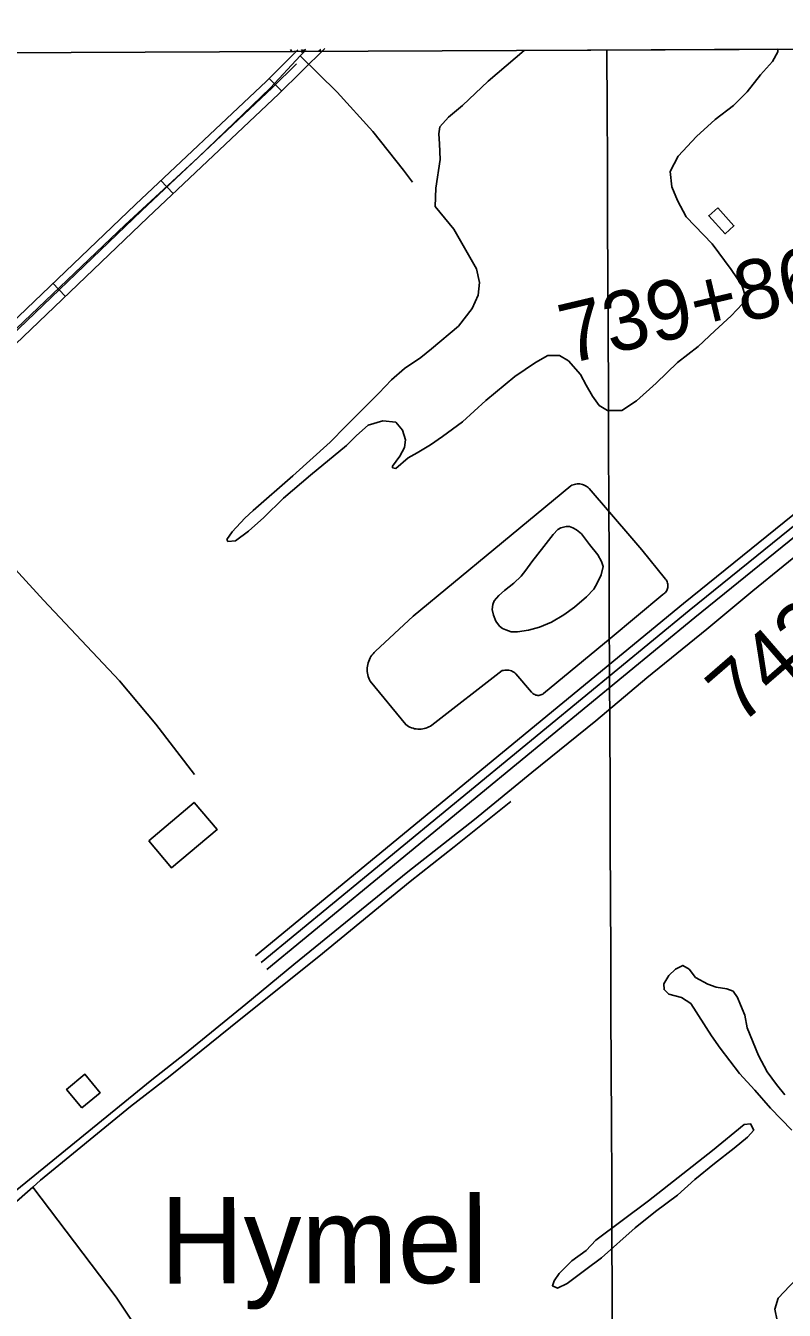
# Model space of a CAD drawing. Extents: x 3419139 to 3457078, y 540382 to 565875.
# Drawn here: x 3432771 to 3434044, y 561886 to 564042 of the extents above; entities that cross this region are included whole.
import ezdxf

# ---------------------------------------------------------------- set-up
doc = ezdxf.new("R2010")
doc.units = 0
for name, color, linetype in [('V-BLDG-OTLN', 7, 'Continuous'), ('V-DTCH-CNTR', 7, 'Continuous'), ('V-GRID-FRAM', 7, 'Continuous'), ('V-GRID-MAJR', 7, 'Continuous'), ('V-ROAD-CNTR', 7, 'Continuous'), ('V-SITE-VEGE', 7, 'Continuous'), ('V-SURV-IDEN', 7, 'Continuous'), ('V-TOPO-GNAM-IDEN', 7, 'Continuous'), ('V-TOPO-SHOR', 7, 'Continuous')]:
    doc.layers.add(name, color=color, linetype=linetype)

msp = doc.modelspace()

# ---------------------------------------------------------------- linework, layer by layer
at = {"layer": 'V-BLDG-OTLN'}
for points in [[(3433932.486, 563736.559), (3433959.841, 563706.183), (3433944.9420000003, 563692.764), (3433917.5870000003, 563723.142)], [(3432977.8000000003, 562674.241), (3433054.029, 562738.556), (3433092.343, 562693.1460000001), (3433016.112, 562628.828)], [(3432865.305231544, 562226.1325213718), (3432896.141169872, 562251.6104704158), (3432870.663220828, 562282.4464087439), (3432839.8272825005, 562256.969459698)]]:
    msp.add_lwpolyline(points, close=True, dxfattribs=at)
at = {"layer": 'V-DTCH-CNTR'}
msp.add_line((3432783.183, 562093.137), (3432923.051, 561908.684), dxfattribs=at)
for points in [[(3432938.477, 563707.723), (3433060.9590000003, 563820.824), (3433182.025, 563937.865), (3433231.957, 563991.1680000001), (3433236.307, 563995.813), (3433239.1768471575, 563998.8765962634)], [(3433236.307, 563995.813), (3433233.7615943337, 563998.8529670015)], [(3433231.957, 563991.1680000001), (3433293.8310000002, 563930.336), (3433353.68, 563864.311), (3433405.0640000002, 563799.696), (3433420.234, 563779.46)], [(3431177.463, 562042.332), (3431253.497, 562110.666), (3431343.14, 562191.228), (3431633.028, 562465.306), (3431891.076, 562710.152), (3431910.889, 562728.951), (3432168.3200000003, 562976.001), (3432453.037, 563247.807), (3432556.0330000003, 563344.78), (3432658.194, 563440.965), (3432938.477, 563707.723)], [(3432556.0330000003, 563344.78), (3432587.38, 563311.062), (3432801.3340000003, 563077.907), (3432928.685, 562942.61)], [(3432928.685, 562942.61), (3432989.757, 562870.042), (3433054.592, 562785.678)], [(3432946.943, 562228.147), (3433013.737, 562279.712), (3433132.537, 562375.681), (3433263.197, 562479.828), (3433416.6720000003, 562605.727), (3433490.411, 562664.06), (3433585.444, 562740.248)], [(3429853.677, 559689.77), (3430082.397, 559876.9720000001), (3430320.146, 560068.611), (3430369.134, 560108.099), (3430639.949, 560331.625), (3430956.687, 560585.09), (3431147.6240000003, 560740.107), (3431172.966, 560760.681), (3431507.447, 561035.132), (3431758.2800000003, 561244.818), (3432070.7600000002, 561502.703), (3432217.62, 561622.799), (3432367.171, 561745.096), (3432625.315, 561955.827), (3432637.14, 561965.481), (3432783.183, 562093.137), (3432796.327, 562104.628), (3432946.943, 562228.147)], [(3433171.662, 561519.687), (3433172.997, 561521.706), (3433174.142, 561523.84), (3433175.09, 561526.066), (3433175.832, 561528.372), (3433176.358, 561530.736), (3433176.669, 561533.136), (3433176.762, 561535.557), (3433176.632, 561537.973), (3433176.284, 561540.3690000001), (3433175.719, 561542.723), (3433174.943, 561545.0160000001), (3433173.96, 561547.228), (3433172.7800000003, 561549.344), (3433171.412, 561551.343), (3433128.203, 561617.155), (3433062.2090000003, 561712.954), (3432984.8910000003, 561816.403), (3432923.051, 561908.684)]]:
    msp.add_lwpolyline(points, dxfattribs=at)
at = {"layer": 'V-GRID-FRAM'}
msp.add_lwpolyline([(3423200.915, 563955.0750000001), (3454837.934, 564093.122), (3454925.2090000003, 545910.191), (3423272.322, 545772.075), (3423200.915, 563955.0750000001)], dxfattribs=at)
at = {"layer": 'V-GRID-MAJR'}
msp.add_spline([(3433823.284, 545818.1140000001), (3433797.732, 551876.0210000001), (3433772.166, 557937.014), (3433746.6010000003, 563998.023), (3433746.588, 564001.091)], degree=3, dxfattribs=at)
at = {"layer": 'V-ROAD-CNTR'}
for p, q in [((3433200.8595604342, 563932.014109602), (3433179.745602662, 563953.326066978)), ((3433018.59192497, 563760.34045295), (3432998.0379660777, 563782.1934092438)), ((3432837.681286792, 563587.9807976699), (3432816.9453282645, 563609.6607543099))]:
    msp.add_line(p, q, dxfattribs=at)
for points in [[(3433228.052506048, 564001.186971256), (3433175.329611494, 563948.9510757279), (3432955.3770514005, 563742.067489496), (3432693.621574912, 563491.7039902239), (3432347.7142667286, 563163.0626475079), (3431998.0889659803, 562828.740316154), (3431714.7705326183, 562560.7748520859), (3431334.6992927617, 562202.1065694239), (3431188.052586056, 562067.0418395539), (3431184.557593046, 562063.880845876), (3431137.0796880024, 562106.8997598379)], [(3433273.38141539, 564003.8669658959), (3433196.167569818, 563927.3651188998), (3432976.023010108, 563720.3015330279), (3432714.3215335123, 563469.9900336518), (3432368.412225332, 563141.34669094), (3432018.762924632, 562807.0003596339), (3431735.372491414, 562538.966895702), (3431355.1572518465, 562180.162613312), (3431208.276545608, 562044.881883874), (3431184.5375930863, 562023.4149268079), (3431183.118595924, 562024.7009242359)], [(3433218.0225261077, 563998.5889764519), (3433215.5525310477, 564001.9519697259)], [(3433241.205479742, 564002.063969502), (3433235.8784903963, 563999.6179743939), (3433234.1044939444, 564002.032969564)], [(3433266.3884293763, 564002.173969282), (3433263.084435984, 563999.266975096)], [(3433225.82151051, 563977.8610179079), (3433185.7485906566, 563938.158097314), (3432965.7000307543, 563731.184511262), (3432703.9715542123, 563480.8470119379), (3432358.06324603, 563152.204669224), (3432008.4259453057, 562817.870337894), (3431725.0715120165, 562549.870873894), (3431344.928272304, 562191.134591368), (3431198.1645658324, 562055.9618617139), (3431184.5475930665, 562043.6478863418), (3431127.0077081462, 562095.7837820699)], [(3434397.952166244, 563492.6499883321), (3434253.7054547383, 563378.1662173), (3433874.924212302, 563072.2048292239), (3433156.9806481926, 562481.481010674)], [(3434407.277147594, 563480.9010118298), (3434263.0804359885, 563366.457240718), (3433884.402193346, 563060.5788524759), (3433166.51162913, 562469.89803384)], [(3434416.6021289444, 563469.152035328), (3434272.455417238, 563354.7482641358), (3433893.88017439, 563048.9528757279), (3433176.0426100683, 562458.3150570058)], [(3433788.683, 563182.198), (3433716.782, 563265.385), (3433715.173, 563266.9400000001), (3433713.43, 563268.341), (3433711.566, 563269.582), (3433709.602, 563270.649), (3433707.548, 563271.5380000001), (3433705.4220000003, 563272.238), (3433703.245, 563272.746), (3433701.0270000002, 563273.055), (3433698.793, 563273.166), (3433696.558, 563273.076), (3433694.338, 563272.787), (3433692.1550000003, 563272.297), (3433690.025, 563271.618), (3433687.963, 563270.747), (3433685.989, 563269.697), (3433556.815, 563163.127), (3433421.698, 563051.245), (3433358.2660000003, 562992.311), (3433356.154, 562990.317), (3433354.19, 562988.178), (3433352.384, 562985.905), (3433350.741, 562983.511), (3433349.273, 562981.006), (3433347.985, 562978.403), (3433346.8850000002, 562975.716), (3433345.975, 562972.958), (3433345.267, 562970.142), (3433344.757, 562967.283), (3433344.45, 562964.395), (3433344.349, 562961.493), (3433344.454, 562958.591), (3433344.7630000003, 562955.705), (3433345.2770000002, 562952.846), (3433345.992, 562950.032), (3433346.901, 562947.276), (3433348.005, 562944.589), (3433349.2970000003, 562941.988), (3433409.089, 562869.2390000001), (3433411.321, 562867.647), (3433413.668, 562866.226), (3433416.111, 562864.983), (3433418.6410000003, 562863.924), (3433421.244, 562863.058), (3433423.9020000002, 562862.386), (3433426.603, 562861.915), (3433429.3310000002, 562861.645), (3433432.073, 562861.579), (3433434.812, 562861.716), (3433437.5330000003, 562862.059), (3433440.22, 562862.601), (3433442.862, 562863.343), (3433445.441, 562864.279), (3433447.941, 562865.403), (3433450.352, 562866.71), (3433452.6580000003, 562868.192), (3433570.864, 562959.724), (3433573.0330000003, 562960.279), (3433575.2430000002, 562960.629), (3433577.477, 562960.7660000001), (3433579.714, 562960.692)], [(3433848.884, 563104.955), (3433848.508, 563106.792), (3433847.932, 563108.578), (3433847.166, 563110.2880000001), (3433846.218, 563111.906), (3433845.1, 563113.41), (3433805.082, 563162.402), (3433788.683, 563182.198)], [(3433579.714, 562960.692), (3433581.934, 562960.408), (3433584.117, 562959.914), (3433586.2430000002, 562959.216), (3433588.295, 562958.321), (3433590.251, 562957.233), (3433592.098, 562955.9670000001), (3433593.8140000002, 562954.534), (3433619.865, 562923.838), (3433621.034, 562922.505), (3433622.359, 562921.328), (3433623.819, 562920.3200000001), (3433625.394, 562919.503), (3433627.057, 562918.884), (3433628.784, 562918.479), (3433630.545, 562918.2880000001), (3433632.321, 562918.3150000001), (3433634.076, 562918.5650000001), (3433635.788, 562919.026), (3433637.43, 562919.697), (3433638.977, 562920.566), (3433640.404, 562921.618), (3433752.252, 563013.719), (3433840.361, 563087.517), (3433841.94, 563088.526), (3433843.4, 563089.704), (3433844.723, 563091.033), (3433845.892, 563092.4990000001), (3433846.894, 563094.083), (3433847.717, 563095.768), (3433848.352, 563097.531), (3433848.788, 563099.354), (3433849.026, 563101.216), (3433849.056, 563103.09), (3433848.884, 563104.955)]]:
    msp.add_lwpolyline(points, dxfattribs=at)
at = {"layer": 'V-SITE-VEGE'}
for p, q in [((3433547.14, 563948.9259999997), (3433607.8895490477, 564000.4854609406)), ((3433607.8895490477, 564000.4854609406), (3434033.285789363, 564002.3416622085)), ((3434033.231, 563998.0700000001), (3434024.21, 563982.018)), ((3434033.285789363, 564002.3416622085), (3434033.231, 563998.0700000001)), ((3434024.21, 563982.018), (3434004.324, 563959.248)), ((3434004.324, 563959.248), (3433981.918, 563931.1229999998)), ((3433504.001, 563908.3279999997), (3433547.14, 563948.9259999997)), ((3433981.918, 563931.1229999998), (3433959.0870000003, 563907.9)), ((3433480.7260000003, 563888.541), (3433504.001, 563908.3279999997)), ((3433466.308, 563872.069), (3433480.7260000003, 563888.541)), ((3433959.0870000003, 563907.9), (3433928.414, 563884.2869999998)), ((3433464.69, 563860.334), (3433466.308, 563872.069)), ((3433928.414, 563884.2869999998), (3433897.1950000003, 563856.2739999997)), ((3433465.4560000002, 563843.669), (3433464.69, 563860.334)), ((3433466.592, 563817.6900000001), (3433465.4560000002, 563843.669)), ((3433897.1950000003, 563856.274), (3433866.395, 563822.865)), ((3433866.395, 563822.865), (3433852.845, 563797.566)), ((3433459.607, 563769.282), (3433466.592, 563817.6900000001)), ((3433852.845, 563797.566), (3433855.452, 563771.569)), ((3433458.232, 563738.4369999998), (3433459.607, 563769.282)), ((3433855.452, 563771.569), (3433864.9590000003, 563748.9139999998)), ((3433489.591, 563700.8069999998), (3433458.232, 563738.4369999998)), ((3433864.9590000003, 563748.9139999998), (3433879.303, 563721.299)), ((3433879.303, 563721.299), (3433923.305, 563676.159)), ((3433527.93, 563634.183), (3433489.591, 563700.8069999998)), ((3433923.305, 563676.159), (3433955.085, 563633.133)), ((3433533.023, 563611.094), (3433527.93, 563634.183)), ((3433955.085, 563633.133), (3433972.87, 563606.4509999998)), ((3433530.3000000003, 563589.5759999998), (3433533.023, 563611.094)), ((3433972.87, 563606.4509999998), (3433979, 563587.757)), ((3433520.707, 563567.162), (3433530.3000000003, 563589.5759999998)), ((3433979, 563587.757), (3433973.9390000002, 563575.086)), ((3433497.794, 563537.5750000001), (3433520.707, 563567.162)), ((3433973.9390000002, 563575.086), (3433955.071, 563555.243)), ((3433955.071, 563555.243), (3433927.806, 563530.116)), ((3433452.242, 563499.947), (3433497.794, 563537.5750000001)), ((3433927.806, 563530.116), (3433899.544, 563503.5349999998)), ((3433434.424, 563485.4779999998), (3433452.242, 563499.947)), ((3433899.544, 563503.5349999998), (3433864.914, 563477.036)), ((3433406.752, 563466.7259999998), (3433434.424, 563485.4779999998)), ((3433647.56, 563488.6319999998), (3433626.83, 563476.651)), ((3433667.149, 563488.382), (3433647.56, 563488.6319999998)), ((3433682.228, 563479.86), (3433667.149, 563488.382)), ((3433702.014, 563456.585), (3433682.228, 563479.86)), ((3433864.914, 563477.036), (3433829.197, 563442.22)), ((3433384.955, 563447.8989999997), (3433406.752, 563466.7259999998)), ((3433626.83, 563476.651), (3433592.239, 563453.0889999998)), ((3433711.5840000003, 563438.827), (3433702.014, 563456.585)), ((3433364.09, 563425.142), (3433384.955, 563447.8989999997)), ((3433592.239, 563453.0889999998), (3433543.231, 563413.054)), ((3433722.613, 563420.071), (3433711.5840000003, 563438.827)), ((3433829.197, 563442.22), (3433795.995, 563412.2739999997)), ((3433308.52, 563370.008), (3433364.09, 563425.142)), ((3433543.231, 563413.054), (3433504.071, 563377.305)), ((3433733.684, 563404.7419999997), (3433722.613, 563420.071)), ((3433795.995, 563412.2739999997), (3433771.787, 563396.4169999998)), ((3433747.781, 563396.234), (3433733.684, 563404.7419999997)), ((3433771.787, 563396.4169999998), (3433747.781, 563396.234)), ((3433282.211, 563342.9099999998), (3433308.52, 563370.008)), ((3433346.258, 563371.4839999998), (3433326.4420000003, 563354.103)), ((3433370.359, 563379.015), (3433346.258, 563371.484)), ((3433392.375, 563376.7719999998), (3433370.359, 563379.0149999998)), ((3433403.471, 563363.405), (3433392.375, 563376.772)), ((3433504.071, 563377.305), (3433470.936, 563352.747)), ((3433326.4420000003, 563354.103), (3433309.576, 563337.6609999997)), ((3433408.6520000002, 563347.1719999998), (3433403.471, 563363.405)), ((3433470.936, 563352.747), (3433450.673, 563338.7980000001)), ((3433219.761, 563286.3959999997), (3433282.211, 563342.9099999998)), ((3433309.576, 563337.6609999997), (3433249.177, 563287.977)), ((3433398.9960000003, 563319.8619999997), (3433407.014, 563333.9670000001)), ((3433407.014, 563333.9670000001), (3433408.6520000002, 563347.1719999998)), ((3433450.673, 563338.7979999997), (3433428.4590000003, 563325.3649999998)), ((3433387.021, 563302.87), (3433398.9960000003, 563319.8619999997)), ((3433413.162, 563316.7429999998), (3433392.359, 563298.8849999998)), ((3433428.4590000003, 563325.3649999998), (3433413.162, 563316.7429999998)), ((3433152.89, 563228.464), (3433219.761, 563286.3959999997)), ((3433249.177, 563287.977), (3433204.1040000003, 563249.3640000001)), ((3433386.985, 563299.9309999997), (3433387.021, 563302.87)), ((3433392.359, 563298.8849999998), (3433386.985, 563299.9309999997)), ((3433204.1040000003, 563249.3640000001), (3433170.863, 563216.477)), ((3433139.011, 563215.414), (3433152.89, 563228.464)), ((3433117.6520000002, 563192.6630000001), (3433139.011, 563215.414)), ((3433170.863, 563216.477), (3433145.099, 563193.781)), ((3433108.668, 563179.5519999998), (3433117.6520000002, 563192.6630000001)), ((3433110.589, 563176.588), (3433108.668, 563179.5519999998)), ((3433123.335, 563177.4049999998), (3433110.589, 563176.5879999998)), ((3433145.099, 563193.781), (3433123.335, 563177.4049999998))]:
    msp.add_line(p, q, dxfattribs=at)
for points in [[(3434057.041, 562188.4670000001), (3434021.322, 562225.61), (3433994.804, 562255.787), (3433969.239, 562283.9940000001), (3433936.522, 562326.478), (3433922.107, 562346.716), (3433887.5810000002, 562400.964), (3433871.574, 562411.439), (3433850.615, 562417.087), (3433842.392, 562424.53), (3433842.028, 562434.317), (3433850.525, 562448.393), (3433861.912, 562459.008), (3433874.218, 562465.211), (3433884.407, 562458.721), (3433894.989, 562444.889), (3433915.883, 562433.863), (3433930.004, 562428.792), (3433947.578, 562426.1190000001), (3433958.289, 562422.0700000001), (3433965.487, 562411.218), (3433970.71, 562398.922), (3433977.826, 562381.71), (3433981.9590000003, 562360.626), (3434000.928, 562313.917), (3434015.258, 562286.829), (3434031.12, 562265.105), (3434045.083, 562247.806)], [(3434032.004, 561869.088), (3434028.336, 561888.21), (3434033.9560000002, 561906.724), (3434053.293, 561927.509), (3434079.542, 561953.095), (3434102.7770000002, 561972.36), (3434126.97, 561990.149), (3434140.2490000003, 561995.851), (3434151.44, 561991.302), (3434165.909, 561975.4670000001), (3434179.759, 561949.367), (3434196.074, 561924.705), (3434223.845, 561877.886)]]:
    msp.add_lwpolyline(points, dxfattribs=at)
msp.add_lwpolyline([(3433727.94, 562003.867), (3433816.344, 562070.238), (3433923.563, 562154.466), (3433976.95, 562198.296), (3433987.72, 562199.135), (3433992.969, 562188.799), (3433982.549, 562177.193), (3433960.296, 562158.403), (3433927.2, 562132.899), (3433894.0840000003, 562105.931), (3433864.8850000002, 562079.401), (3433827.849, 562051.993), (3433793.754, 562025.037), (3433737.344, 561974.4), (3433711.169, 561954.68), (3433680.058, 561931.599), (3433663.813, 561923.491), (3433655.06, 561927.515), (3433658.1010000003, 561935.789), (3433666.578, 561948.401), (3433687.883, 561969.651), (3433711.58, 561986.956)], close=True, dxfattribs=at)
at = {"layer": 'V-TOPO-SHOR'}
for points in [[(3434391.16, 563433.774), (3434392.5160000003, 563424.941), (3434390.4250000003, 563414.683), (3434376.0810000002, 563403.603), (3434316.723, 563357.832), (3434244.961, 563299.4890000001), (3434170.74, 563240.1950000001), (3434093.0330000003, 563176.539), (3433991.571, 563093.5970000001), (3433914.347, 563029.446), (3433813.395, 562947.966), (3433727.739, 562875.596), (3433620.35, 562788.812), (3433524.326, 562709.718), (3433412.517, 562622.008), (3433317, 562544.379), (3433221.484, 562466.745), (3433140.801, 562400.189), (3433037.858, 562316.287), (3432983.072, 562273.183)], [(3433566.6350000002, 563034.2170000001), (3433560.383, 563042.616), (3433556.111, 563052.946), (3433553.784, 563062.273), (3433555.357, 563070.574), (3433557.395, 563076.908), (3433565.343, 563086.104), (3433574.745, 563094.304), (3433590.5640000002, 563106.823), (3433602.457, 563118.417), (3433610.415, 563128.589), (3433620.864, 563142.157), (3433640.773, 563168.329), (3433656.196, 563188.194), (3433664.13, 563196.411), (3433669.549, 563199.278), (3433678.3880000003, 563201.611), (3433683.771, 563201.5430000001), (3433689.616, 563199.512), (3433695.4420000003, 563196.012), (3433703.679, 563189.544), (3433717.147, 563171.2660000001), (3433731.116, 563153.962), (3433737.34, 563143.116), (3433740.162, 563134.273), (3433737.051, 563120.61), (3433730.021, 563106.51), (3433724.507, 563096.303), (3433712.115, 563083.738), (3433692.319, 563066.375), (3433674.536, 563053.3910000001), (3433653.825, 563040.933), (3433633.6580000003, 563032.872), (3433614.9990000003, 563027.727), (3433596.3680000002, 563025.03), (3433586.093, 563025.161), (3433577.215, 563028.227), (3433571.485, 563030.73), (3433566.6350000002, 563034.2170000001)], [(3432983.072, 562273.183), (3432732.1550000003, 562068.778), (3432622.515, 561978.764)]]:
    msp.add_lwpolyline(points, dxfattribs=at)

# ---------------------------------------------------------------- texts
at = {"layer": 'V-SURV-IDEN'}
for s, rotation, p in [('739+86.8', 13.310555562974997, (3433680.8780306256, 563473.9770304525)), ('743+24.1', 40.904736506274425, (3433969.7854528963, 562866.58362781))]:
    msp.add_text(s, height=100, rotation=rotation, dxfattribs=at).set_placement(p)
at = {"layer": 'V-TOPO-GNAM-IDEN'}
msp.add_text('Hymel', height=144.99971199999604, rotation=0.08799162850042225, dxfattribs=at).set_placement((3432997.125967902, 561931.3321109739))

doc.saveas('drawing.dxf')
